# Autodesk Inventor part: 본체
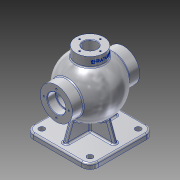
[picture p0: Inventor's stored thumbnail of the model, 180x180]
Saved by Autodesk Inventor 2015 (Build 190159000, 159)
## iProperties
Created: 2025-08
Part Number: 본체
Material: 알루미늄 6061
Document SubType Name: Modeling
Designer: USER
Density: 2.7 g/cm^3
Appearance: 알루미늄 - 평지
Mass: 1526.72 g
Surface Area: 1173.82 cm^2
Volume: 565.453 cm^3
Author: USER
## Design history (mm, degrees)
sketch "스케치1"
  geometry: L1 (-62.5, -62.5)-(62.5, -62.5); L2 (62.5, -62.5)-(62.5, 62.5); L3 (62.5, 62.5)-(-62.5, 62.5); L4 (-62.5, 62.5)-(-62.5, -62.5); L5 (-62.5, -62.5)-(62.5, 62.5); L6 (62.5, -62.5)-(-62.5, 62.5); 1 further point
  constraints: 12 end point, 2 midpoint, 2 parallel, 1 horizontal, 1 perpendicular
  dimensions: "d0" = 125 distance of L3.end L2.end; "d1" = 125 distance of L2.end L1.end
extrude "돌출1" new body sketch "스케치1" distance "d2" = 10; taper "d3" = 0 deg
fillet "모깎기1" dims "d4" = 16
sketch "스케치2"
  geometry: L1 (62.5, 10)-(62.5, 0) reference; L2 (62.5, 0)-(-62.5, 0) reference; L3 (-62.5, 0)-(-62.5, 10) reference; L4 (-62.5, 10)-(62.5, 10) reference; L5 (0, 0)-(0, 85); L6 (-65, 85)-(65, 85); L7 (-65, 85)-(-65, 116); L8 (-65, 116)-(-44.215, 116); L9 (65, 116)-(65, 85); L10 (65, 116)-(44.215, 116); A1 r 54 centre (0, 85) between (54, 85) and (-54, 85); A2 r 44 centre (0, 85) between (44, 85) and (-44, 85); 1 further point
  constraints: 12 end point, 6 point on circle, 6 point on line, 2 centre point, 2 coincident, 2 perpendicular, 2 vertical, 1 horizontal, 1 midpoint
  dimensions: "d5" = 85 distance of L5.end L5.start; "d6" = 108 diameter of A1; "d7" = 88 diameter of A2; "d8" = 130 distance of L6.start L6.end; "d9" = 31 distance of L6.start L7.end
revolve "회전1" sketch "스케치2" stored, may be unused: angle "d10" = 90 deg
node "작업 평면1"
sketch "스케치3"
  geometry: C1 r 27 at (0, 0); 1 further point
  constraints: 1 centre point, 1 coincident
  dimensions: "d12" = 54 diameter of C1
extrude "돌출2" join sketch "스케치3" stored distance "d13" = 10; taper "d14" = 0 deg
sketch "스케치5"
  geometry: L1 (46.5, -62.5)-(-46.5, -62.5) reference; L2 (-62.5, -46.5)-(-62.5, 46.5) reference; L3 (-46.5, 62.5)-(46.5, 62.5) reference; L4 (62.5, 46.5)-(62.5, -46.5) reference; L5 (-4, 50.5)-(4, 50.5); L6 (4, 50.5)-(4, -50.5); L7 (4, -50.5)-(-4, -50.5); L8 (-4, -50.5)-(-4, 50.5); L9 (-50.5, 4)-(50.5, 4); L10 (50.5, 4)-(50.5, -4); L11 (50.5, -4)-(-50.5, -4); L12 (-50.5, -4)-(-50.5, 4); A1 r 16 centre (46.5, -46.5) between (46.5, -62.5) and (62.5, -46.5) reference; A2 r 16 centre (-46.5, -46.5) between (-62.5, -46.5) and (-46.5, -62.5) reference; A3 r 16 centre (-46.5, 46.5) between (-46.5, 62.5) and (-62.5, 46.5) reference; A4 r 16 centre (46.5, 46.5) between (62.5, 46.5) and (46.5, 62.5) reference; 3 further points
  constraints: 16 end point, 4 parallel, 2 horizontal, 2 midpoint, 2 perpendicular, 1 horizontal alignment, 1 vertical alignment
  dimensions: "d19" = 8 distance of L6.end L7.end; "d20" = 12 distance between parallel lines of L4 L10; "d21" = 12 distance between parallel lines of L2 L12; "d22" = 12 distance between parallel lines of L3 L5; "d23" = 12 distance between parallel lines of L1 L7; "d24" = 8 distance of L9.end L10.end
extrude "돌출3" join sketch "스케치5" stored distance "d25" = 8; taper "d26" = 0 deg
feature "면 기울기1" dims angle "d27" = 20 deg
feature "면 기울기2" dims angle "d28" = 20 deg
feature "면 기울기3" dims angle "d29" = 20 deg
feature "면 기울기4" dims angle "d30" = 20 deg
hole "구멍1" diameter "d33" = 30; stored, may be unused: countersink angle "d37" = 90 deg, drill point angle "d39" = 0 deg; dims "d31" = 10, "d32" = 10, "d34" = 6, "d35" = 35, "d36" = 16, "d38" = 8
hole "구멍2" diameter "d42" = 35; stored, may be unused: countersink angle "d46" = 90 deg, drill point angle "d48" = 0 deg; dims "d40" = 10, "d41" = 10, "d43" = 6, "d44" = 35, "d45" = 16, "d47" = 16
chamfer "모따기2" distance "d52" = 1; stored, may be unused: second distance "d53" = 2, angle "d54" = 45 deg
sketch "스케치6"
  geometry: C1 r 13 at (0, 0); 1 further point
  constraints: 1 centre point, 1 coincident
  dimensions: "d55" = 26 diameter of C1
extrude "돌출4" cut sketch "스케치6" stored distance "d56" = 8; taper "d57" = 0 deg
chamfer "모따기3" distance "d58" = 1; stored, may be unused: second distance "d59" = 2, angle "d60" = 45 deg
sketch "스케치7"
  geometry: L1 (0, 0)-(0, 24); L2 (13, 42.036)-(-13, 42.036) reference; C1 r 18.5 at (0, 0) reference; C2 r 31 at (0, 0) reference; 1 further point
  constraints: 2 end point, 1 perpendicular
  dimensions: "d61" = 24 distance of L1.start L1.end
hole "구멍3" sketch "스케치7" at (0, 24) diameter "d62" = 3.242; stored, may be unused: countersink angle "d66" = 90 deg, drill point angle "d68" = 118 deg; dims "d63" = 12, "d64" = 35, "d65" = 16, "d67" = 15
fillet "모깎기2" dims "d72" = 0.6
sketch "스케치8"
  geometry: L1 (0, 0)-(0, 20); C1 r 14 at (0, 0) reference; C2 r 27 at (0, 0) reference; 1 further point
  constraints: 2 end point, 1 vertical
  dimensions: "d73" = 20 distance of L1.start L1.end
hole "구멍4" sketch "스케치8" at (0, 20) diameter "d74" = 3.242; stored, may be unused: countersink angle "d78" = 90 deg, drill point angle "d80" = 118 deg; dims "d75" = 9, "d76" = 35, "d77" = 16, "d79" = 11
fillet "모깎기3" dims "d84" = 3
fillet "모깎기4" dims "d85" = 3
fillet "모깎기5" dims "d86" = 3
fillet "모깎기6" dims "d87" = 3
fillet "모깎기7" dims "d88" = 3
fillet "모깎기8" dims "d89" = 3
fillet "모깎기9" dims "d90" = 3
sketch "스케치9"
  geometry: L1 (-46.5, 46.5)-(46.5, 46.5); L2 (46.5, 46.5)-(46.5, -46.5); L3 (46.5, -46.5)-(-46.5, -46.5); L4 (-46.5, -46.5)-(-46.5, 46.5); L5 (-46.5, 46.5)-(46.5, -46.5); L6 (46.5, 46.5)-(-46.5, -46.5); 1 further point
  constraints: 12 end point, 2 midpoint, 2 parallel, 1 horizontal, 1 perpendicular
  dimensions: "d91" = 93 distance of L2.end L3.end; "d92" = 93 distance of L1.end L2.end
hole "구멍5" sketch "스케치9" at (-46.5, -46.5) diameter "d93" = 11; stored, may be unused: countersink angle "d97" = 90 deg, drill point angle "d99" = 0 deg; dims "d94" = 8, "d95" = 35, "d96" = 16, "d98" = 11
sketch "스케치10"
  geometry: L1 (14, 150)-(-14, 150) reference; L2 (-50, 59.379)-(-49.026, 61) reference; L3 (-49.026, 61)-(-50, 62.621) reference; L4 (-50, 62.621)-(-65, 62.621) reference; L5 (-65, 62.621)-(-65, 66.5) reference; L6 (-65, 66.5)-(-64, 67.5) reference; L7 (-64, 67.5)-(-49.6, 67.5) reference; L8 (-49, 68.1)-(-49, 70) reference; L9 (-49, 70)-(-41.364, 70) reference; L10 (41.364, 70)-(49, 70) reference; L11 (49, 70)-(49, 68.1) reference; L12 (49.6, 67.5)-(64, 67.5) reference; L13 (64, 67.5)-(65, 66.5) reference; L14 (65, 66.5)-(65, 62.621) reference; L15 (65, 62.621)-(50, 62.621) reference; L16 (50, 62.621)-(49.026, 61) reference; L17 (49.026, 61)-(50, 59.379) reference; L18 (50, 59.379)-(65, 59.379) reference; L19 (65, 59.379)-(65, 54) reference; L20 (65, 54)-(45.749, 54) reference; L21 (38.041, 44.231)-(49.782, 11.974) reference; L22 (52.601, 10)-(59.5, 10) reference; L23 (62.5, 7)-(62.5, 0) reference; L24 (62.5, 0)-(-62.5, 0) reference; L25 (-62.5, 0)-(-62.5, 7) reference; L26 (-59.5, 10)-(-52.601, 10) reference; L27 (-49.782, 11.974)-(-38.041, 44.231) reference; L28 (-45.749, 54)-(-65, 54) reference; L29 (-65, 54)-(-65, 59.379) reference; L30 (-65, 59.379)-(-50, 59.379) reference; L31 (-14, 150)-(-13, 149) reference; L32 (-13, 149)-(-13, 127.036) reference; L33 (-41.364, 100)-(-49, 100) reference; L34 (-49, 100)-(-49, 101.9) reference; L35 (-49.6, 102.5)-(-64, 102.5) reference; L36 (-64, 102.5)-(-65, 103.5) reference; L37 (-65, 103.5)-(-65, 107.379) reference; L38 (-65, 107.379)-(-50, 107.379) reference; L39 (-50, 107.379)-(-49.026, 109) reference; L40 (-49.026, 109)-(-50, 110.621) reference; L41 (-50, 110.621)-(-65, 110.621) reference; L42 (-65, 110.621)-(-65, 116) reference; L43 (-65, 116)-(-45.749, 116) reference; L44 (-27, 133.466)-(-27, 150) reference; L45 (-27, 150)-(-21.621, 150) reference; L46 (-21.621, 150)-(-21.621, 139) reference; L47 (-21.621, 139)-(-20, 138.026) reference; L48 (-20, 138.026)-(-18.379, 139) reference; L49 (-18.379, 139)-(-18.379, 150) reference; L50 (-18.379, 150)-(-14, 150) reference; L51 (13, 149)-(14, 150) reference; L52 (14, 150)-(18.379, 150) reference; L53 (18.379, 150)-(18.379, 139) reference; L54 (18.379, 139)-(20, 138.026) reference; L55 (20, 138.026)-(21.621, 139) reference; L56 (21.621, 139)-(21.621, 150) reference; L57 (21.621, 150)-(27, 150) reference; L58 (27, 150)-(27, 133.466) reference; L59 (45.749, 116)-(65, 116) reference; L60 (65, 116)-(65, 110.621) reference; L61 (65, 110.621)-(50, 110.621) reference; L62 (50, 110.621)-(49.026, 109) reference; L63 (49.026, 109)-(50, 107.379) reference; L64 (50, 107.379)-(65, 107.379) reference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; A1 r 0.6 centre (-49.6, 68.1) between (-49.6, 67.5) and (-49, 68.1) reference; A2 r 44 centre (0, 85) between (-41.364, 70) and (41.364, 70) reference; A3 r 0.6 centre (49.6, 68.1) between (49, 68.1) and (49.6, 67.5) reference; A4 r 3 centre (45.749, 51) between (45.749, 54) and (43.341, 52.789) reference; A5 r 54 centre (0, 85) between (38.709, 47.349) and (43.341, 52.789) reference; A6 r 3 centre (40.86, 45.257) between (38.709, 47.349) and (38.041, 44.231) reference; A7 r 3 centre (52.601, 13) between (49.782, 11.974) and (52.601, 10) reference; A8 r 3 centre (59.5, 7) between (62.5, 7) and (59.5, 10) reference; A9 r 3 centre (-59.5, 7) between (-59.5, 10) and (-62.5, 7) reference; A10 r 3 centre (-52.601, 13) between (-52.601, 10) and (-49.782, 11.974) reference; A11 r 3 centre (-40.86, 45.257) between (-38.041, 44.231) and (-38.709, 47.349) reference; A12 r 54 centre (0, 85) between (-43.341, 52.789) and (-38.709, 47.349) reference; A13 r 3 centre (-45.749, 51) between (-43.341, 52.789) and (-45.749, 54) reference; A14 r 44 centre (0, 85) between (-13, 127.036) and (-41.364, 100) reference; A15 r 0.6 centre (-49.6, 101.9) between (-49, 101.9) and (-49.6, 102.5) reference; A16 r 3 centre (-45.749, 119) between (-45.749, 116) and (-43.341, 117.211) reference; A17 r 54 centre (0, 85) between (-28.421, 130.916) and (-43.341, 117.211) reference; A18 r 3 centre (-30, 133.466) between (-28.421, 130.916) and (-27, 133.466) reference; A19 r 3 centre (30, 133.466) between (27, 133.466) and (28.421, 130.916) reference; A20 r 54 centre (0, 85) between (43.341, 117.211) and (28.421, 130.916) reference; A21 r 3 centre (45.749, 119) between (43.341, 117.211) and (45.749, 116) reference; A22 r 0.6 centre (49.6, 101.9) between (49.6, 102.5) and (49, 101.9) reference; A23 r 44 centre (0, 85) between (41.364, 100) and (13, 127.036) reference; 2 further points
  constraints: 1 vertical alignment, 1 other
  dimensions: "d106" = 9 distance from line of L1 point (0, 141)
feature "엠보싱1" sketch "스케치10" dims "d5" = 85, "d6" = 108, "d7" = 88, "d8" = 130, "d9" = 31, "d107" = 0.5, "d108" = 0
node "솔리드1"
pattern_circular "원형 패턴1" dims angle "d70" = 360 deg
mirror "대칭1"
pattern_circular "원형 패턴2" dims angle "d82" = 360 deg
pattern_linear "직사각형 패턴1" dims "d102" = 93, "d105" = 93
node "절단 모서리 투영1"
node "절단 모서리 투영3"
node "절단 모서리 투영4"
node "절단 모서리 투영5"
node "절단 모서리 투영6"
